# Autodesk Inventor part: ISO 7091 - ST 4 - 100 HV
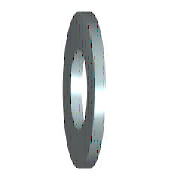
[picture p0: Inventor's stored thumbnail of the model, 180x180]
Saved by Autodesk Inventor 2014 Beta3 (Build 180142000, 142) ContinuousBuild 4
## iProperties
IsCustomPart: 0
Created: 2010-02
Part Number: ISO 7091 - ST 4 - 100 HV
Material: Steel
Description: Plain washers - Normal series - Product grade C
Document SubType Name: Modeling
Standard: ISO 7091
Designer: Thom Tremblay
Standard Revision: Second edition 2000-06-01
Standards Organization: ISO
Language: en-US
Size Designation: ST 4 - 100 HV
Categories: <MemberInstance><Categories><Category DisplayName="Fasteners" InternalName="e4da775c-781d-43d5-af7c-5136215cf5a6" Mnemonic="FSTN"><Category DisplayName="Washers
Density: 7.85 g/cm^3
Appearance: Steel
Author: Thom Tremblay
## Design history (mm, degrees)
sketch "Sketch"
  geometry: C1 r 5 at (0, 0); C2 r 2.25 at (0, 0); 1 further point
  constraints: 2 centre point, 2 coincident
  dimensions: "d0" = 4.5 diameter of C2 (= SD1); "d1" = 10 diameter of C1 (= SD2)
extrude "Body" new body sketch "Sketch" distance "d2" = 1 (= SD); taper "d3" = 0 deg
workaxis "Work Axis1"
workplane "Work Plane1"
body "Solid1"
other parameters: "SD1" = 4.5 [user parameter; used in 1 equation term], "SD2" = 10 [user parameter; used in 1 equation term], "SD" = 1 [user parameter; used in 1 equation term], "d4" = 0, "d5" = 0, "d6" = 0, "d7" = 0, "NND" = 4 [user parameter]
